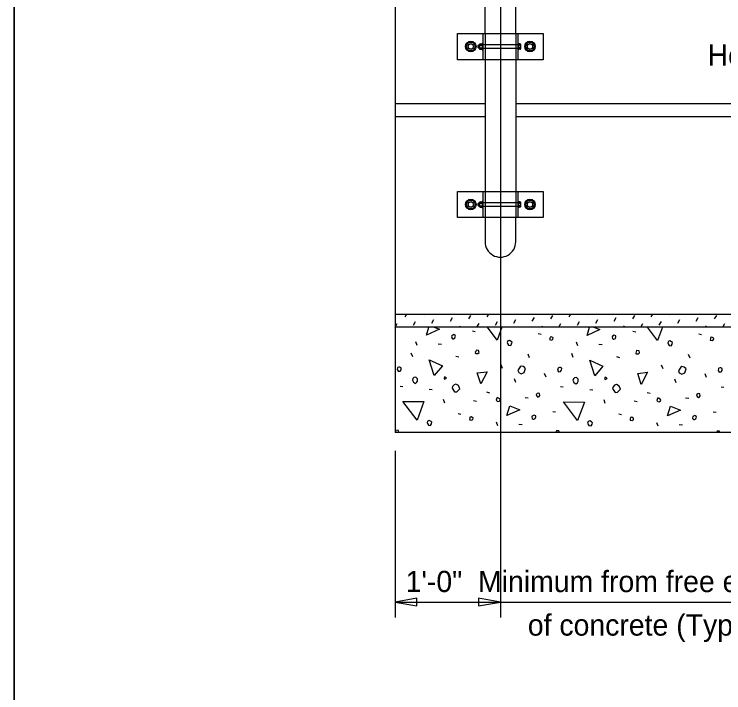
# Model space of a CAD drawing. Extents: x 0 to 41.1, y 0 to 25.9.
# Drawn here: x 0 to 6.74, y 10.63 to 17.07 of the extents above; entities that cross this region are included whole.
import ezdxf

# ---------------------------------------------------------------- set-up
doc = ezdxf.new("R2010")
doc.units = 0
for name, color, linetype in [('ActivePts-ConstElements', 7, 'Continuous'), ('CL_Major', 7, 'Continuous'), ('Dimension', 7, 'Continuous'), ('Miscellaneous', 7, 'Continuous'), ('Miscellaneous1', 7, 'Continuous'), ('SteelMisc', 7, 'Continuous'), ('SteelMisc_h', 7, 'Continuous'), ('SupstrConc', 7, 'Continuous'), ('TextStructures', 7, 'Continuous')]:
    doc.layers.add(name, color=color, linetype=linetype)

msp = doc.modelspace()

# ---------------------------------------------------------------- linework, layer by layer
at = {"layer": 'ActivePts-ConstElements'}
msp.add_lwpolyline([(0, 0), (41.0506, 0), (41.0506, 25.9461), (0, 25.9461)], close=True, dxfattribs=at)
at = {"layer": 'CL_Major'}
msp.add_line((4.615, 25.5927), (4.615, 11.342), dxfattribs=at)
at = {"layer": 'Dimension'}
for p, q in [((3.615, 12.9261), (3.615, 11.342)), ((3.6151, 11.4901), (8.3895, 11.4901))]:
    msp.add_line(p, q, dxfattribs=at)
for points in [[(3.6151, 11.4901), (3.8233, 11.4549), (3.8233, 11.5254)], [(4.6151, 11.4902), (4.4068, 11.5255), (4.4068, 11.4549)]]:
    msp.add_lwpolyline(points, close=True, dxfattribs=at)
at = {"layer": 'Miscellaneous'}
for p, q in [((4.4075, 16.7575), (4.4075, 16.7696)), ((4.4132, 16.7575), (4.4132, 16.7696)), ((4.4075, 15.2575), (4.4075, 15.2696)), ((4.4132, 15.2575), (4.4132, 15.2696)), ((3.7123, 14.1967), (3.7283, 14.2245)), ((3.8873, 14.2162), (3.8921, 14.2245)), ((4.4901, 14.1967), (4.5062, 14.2245)), ((4.6651, 14.2162), (4.6699, 14.2245)), ((5.2679, 14.1967), (5.284, 14.2245)), ((5.4429, 14.2162), (5.4477, 14.2245)), ((6.0457, 14.1967), (6.0618, 14.2245)), ((6.2207, 14.2162), (6.2255, 14.2245)), ((3.7901, 14.119), (3.8095, 14.1526)), ((3.9651, 14.1384), (3.9845, 14.172)), ((4.1401, 14.1579), (4.1595, 14.1914)), ((4.3151, 14.1773), (4.3345, 14.2109)), ((4.5679, 14.119), (4.5873, 14.1526)), ((4.7429, 14.1384), (4.7623, 14.172)), ((4.9179, 14.1579), (4.9373, 14.1914)), ((5.0929, 14.1773), (5.1123, 14.2109)), ((5.3457, 14.119), (5.3651, 14.1526)), ((5.5207, 14.1384), (5.5401, 14.172)), ((5.6957, 14.1579), (5.7152, 14.1914)), ((5.8707, 14.1773), (5.8902, 14.2109)), ((6.1235, 14.119), (6.143, 14.1526)), ((6.2985, 14.1384), (6.318, 14.172)), ((6.4735, 14.1579), (6.493, 14.1914)), ((6.6485, 14.1773), (6.668, 14.2109)), ((3.615, 14.0995), (3.6345, 14.1331)), ((4.2291, 14.0995), (4.2373, 14.1137)), ((4.3929, 14.0995), (4.4123, 14.1331)), ((5.0069, 14.0995), (5.0151, 14.1137)), ((5.1707, 14.0995), (5.1901, 14.1331)), ((5.7847, 14.0995), (5.7929, 14.1137)), ((5.9485, 14.0995), (5.9679, 14.1331)), ((6.5626, 14.0995), (6.5708, 14.1137)), ((6.7263, 14.0995), (6.7458, 14.1331)), ((4.3489, 14.0642), (4.3754, 14.0589)), ((4.9746, 14.0394), (5.0012, 14.0341)), ((5.8727, 14.0606), (5.8992, 14.0553)), ((6.4985, 14.0359), (6.525, 14.0306)), ((3.8256, 13.9263), (3.8132, 13.9599)), ((5.3494, 13.9227), (5.337, 13.9563)), ((4.0254, 13.9422), (4.0572, 13.9387)), ((5.5492, 13.9387), (5.581, 13.9351)), ((3.7832, 13.8167), (3.769, 13.852)), ((4.1933, 13.8237), (4.2216, 13.8167)), ((4.8916, 13.8078), (4.8774, 13.8432)), ((5.307, 13.8131), (5.2928, 13.8485)), ((5.7171, 13.8202), (5.7454, 13.8131)), ((6.4154, 13.8043), (6.4012, 13.8397)), ((4.6352, 13.7071), (4.6211, 13.7424)), ((6.1591, 13.7035), (6.1449, 13.7389)), ((4.7607, 13.5745), (4.7484, 13.6081)), ((5.0489, 13.6258), (5.0348, 13.6611)), ((6.5727, 13.6222), (6.5586, 13.6576)), ((3.663, 13.5409), (3.6877, 13.5374)), ((6.2846, 13.571), (6.2722, 13.6045)), ((3.9387, 13.5126), (3.9688, 13.5073)), ((4.4832, 13.4843), (4.5115, 13.4773)), ((5.1868, 13.5374), (5.2115, 13.5338)), ((5.4626, 13.5091), (5.4926, 13.5038)), ((6.007, 13.4808), (6.0353, 13.4737)), ((6.7106, 13.5338), (6.7353, 13.5303)), ((4.0872, 13.3783), (4.0749, 13.4119)), ((4.3612, 13.4048), (4.3895, 13.3977)), ((4.8491, 13.4331), (4.8792, 13.4278)), ((5.611, 13.3747), (5.5987, 13.4083)), ((6.373, 13.4295), (6.403, 13.4242)), ((5.885, 13.4013), (5.9133, 13.3942)), ((3.615, 13.2988), (3.6152, 13.2987)), ((4.2145, 13.2793), (4.241, 13.274)), ((5.1125, 13.3005), (5.1391, 13.2952)), ((5.7383, 13.2757), (5.7648, 13.2704)), ((6.6363, 13.297), (6.6629, 13.2917)), ((4.5893, 13.1626), (4.5769, 13.1962)), ((4.789, 13.1785), (4.8209, 13.175)), ((6.1131, 13.1591), (6.1007, 13.1927)), ((6.3128, 13.175), (6.3447, 13.1714))]:
    msp.add_line(p, q, dxfattribs=at)
for points in [[(3.914, 14.0253), (3.9368, 14.0995)], [(3.9869, 14.0995), (4.036, 14.0801), (3.914, 14.0253)], [(4.584, 13.9775), (4.4913, 14.0995)], [(4.6296, 14.0995), (4.584, 13.9775)], [(5.4378, 14.0217), (5.4617, 14.0995)], [(5.5018, 14.0995), (5.5598, 14.0765), (5.4378, 14.0217)], [(6.1078, 13.974), (6.0124, 14.0995)], [(6.1547, 14.0995), (6.1078, 13.974)], [(4.1615, 13.9899), (4.1685, 13.9899), (4.1827, 13.997), (4.188, 14.0129), (4.1862, 14.0217), (4.1721, 14.0288), (4.1544, 14.0182), (4.1509, 14.0076), (4.1544, 13.997), (4.1615, 13.9899)], [(5.6853, 13.9864), (5.6924, 13.9864), (5.7065, 13.9935), (5.7118, 14.0094), (5.71, 14.0182), (5.6959, 14.0253), (5.6782, 14.0147), (5.6747, 14.0041), (5.6782, 13.9935), (5.6853, 13.9864)], [(4.683, 13.9457), (4.6918, 13.9298), (4.713, 13.9263), (4.7219, 13.9422), (4.7254, 13.9563), (4.7166, 13.9652), (4.7006, 13.974), (4.6847, 13.9687), (4.6794, 13.9528), (4.683, 13.9457)], [(5.0825, 13.9811), (5.1019, 13.9758), (5.1143, 13.9846), (5.1161, 13.997), (5.1125, 14.0005), (5.0984, 14.0076), (5.086, 14.0058), (5.0843, 13.9935), (5.0825, 13.9811)], [(6.2068, 13.9422), (6.2156, 13.9263), (6.2368, 13.9227), (6.2457, 13.9387), (6.2492, 13.9528), (6.2404, 13.9616), (6.2245, 13.9705), (6.2086, 13.9652), (6.2032, 13.9493), (6.2068, 13.9422)], [(6.6063, 13.9775), (6.6257, 13.9722), (6.6381, 13.9811), (6.6399, 13.9935), (6.6363, 13.997), (6.6222, 14.0041), (6.6098, 14.0023), (6.6081, 13.9899), (6.6063, 13.9775)], [(4.3807, 13.8485), (4.4019, 13.8485), (4.4125, 13.8591), (4.4072, 13.8786), (4.3842, 13.8803), (4.3807, 13.8697), (4.3754, 13.8609), (4.3807, 13.8485), (4.3771, 13.852)], [(5.9045, 13.845), (5.9257, 13.845), (5.9363, 13.8556), (5.931, 13.875), (5.908, 13.8768), (5.9045, 13.8662), (5.8992, 13.8573), (5.9045, 13.845), (5.901, 13.8485)], [(3.9865, 13.6417), (3.9387, 13.7884), (4.0642, 13.7336), (3.9865, 13.6417)], [(5.5103, 13.6381), (5.4626, 13.7849), (5.5881, 13.7301), (5.5103, 13.6381)], [(3.6347, 13.6965), (3.6435, 13.6806), (3.663, 13.6823), (3.6718, 13.6947), (3.6736, 13.7141), (3.6612, 13.7195), (3.6524, 13.7212), (3.6418, 13.7177), (3.6382, 13.7141), (3.6347, 13.6965)], [(4.4284, 13.5604), (4.3948, 13.6647), (4.4885, 13.677), (4.4284, 13.5604)], [(4.789, 13.67), (4.812, 13.6576), (4.8421, 13.67), (4.8544, 13.7071), (4.8368, 13.7248), (4.8138, 13.7301), (4.8032, 13.723), (4.7908, 13.7035), (4.782, 13.6876), (4.789, 13.67)], [(5.1585, 13.6929), (5.1673, 13.677), (5.1868, 13.6788), (5.1956, 13.6912), (5.1974, 13.7106), (5.185, 13.7159), (5.1762, 13.7177), (5.1656, 13.7141), (5.162, 13.7106), (5.1585, 13.6929)], [(6.3128, 13.6664), (6.3358, 13.654), (6.3659, 13.6664), (6.3783, 13.7035), (6.3606, 13.7212), (6.3376, 13.7265), (6.327, 13.7195), (6.3146, 13.7), (6.3058, 13.6841), (6.3128, 13.6664)], [(6.6823, 13.6894), (6.6912, 13.6735), (6.7106, 13.6753), (6.7194, 13.6876), (6.7212, 13.7071), (6.7088, 13.7124), (6.7, 13.7141), (6.6894, 13.7106), (6.6858, 13.7071), (6.6823, 13.6894)], [(3.7796, 13.5975), (3.7902, 13.5763), (3.8079, 13.5657), (3.8221, 13.5763), (3.8291, 13.5869), (3.8291, 13.6081), (3.8132, 13.624), (3.7938, 13.6222), (3.7849, 13.6134), (3.7796, 13.5975)], [(4.0855, 13.6063), (4.1049, 13.6152), (4.0978, 13.6222), (4.0855, 13.6275), (4.0802, 13.6152), (4.0855, 13.6063)], [(5.3035, 13.5939), (5.3141, 13.5727), (5.3317, 13.5621), (5.3459, 13.5727), (5.353, 13.5833), (5.353, 13.6045), (5.337, 13.6205), (5.3176, 13.6187), (5.3088, 13.6098), (5.3035, 13.5939)], [(5.6093, 13.6028), (5.6287, 13.6116), (5.6217, 13.6187), (5.6093, 13.624), (5.604, 13.6116), (5.6093, 13.6028)], [(5.9522, 13.5568), (5.9186, 13.6611), (6.0123, 13.6735), (5.9522, 13.5568)], [(4.1562, 13.5215), (4.1792, 13.4843), (4.2021, 13.4861), (4.211, 13.4949), (4.2304, 13.5144), (4.218, 13.5444), (4.1933, 13.5586), (4.1756, 13.5515), (4.1615, 13.5374), (4.1562, 13.5215)], [(5.68, 13.5179), (5.703, 13.4808), (5.7259, 13.4826), (5.7348, 13.4914), (5.7542, 13.5109), (5.7419, 13.5409), (5.7171, 13.555), (5.6994, 13.548), (5.6853, 13.5338), (5.68, 13.5179)], [(4.9605, 13.4454), (4.9711, 13.4348), (4.9817, 13.4419), (4.9888, 13.4525), (4.9853, 13.4702), (4.9764, 13.472), (4.964, 13.4702), (4.9534, 13.4596), (4.9605, 13.4454)], [(4.5857, 13.3959), (4.5981, 13.3942), (4.6105, 13.3995), (4.614, 13.4101), (4.6087, 13.4189), (4.5981, 13.426), (4.5857, 13.4313), (4.5787, 13.4172), (4.5751, 13.4066), (4.5857, 13.3959)], [(6.1096, 13.3924), (6.1219, 13.3906), (6.1343, 13.3959), (6.1378, 13.4066), (6.1325, 13.4154), (6.1219, 13.4225), (6.1096, 13.4278), (6.1025, 13.4136), (6.0989, 13.403), (6.1096, 13.3924)], [(6.4843, 13.4419), (6.4949, 13.4313), (6.5055, 13.4384), (6.5126, 13.449), (6.5091, 13.4667), (6.5002, 13.4684), (6.4879, 13.4667), (6.4773, 13.4561), (6.4843, 13.4419)], [(3.8238, 13.2174), (3.6895, 13.3942), (3.8892, 13.3924), (3.8238, 13.2174)], [(4.6777, 13.2616), (4.7059, 13.3535), (4.7996, 13.3164), (4.6777, 13.2616)], [(5.3476, 13.2139), (5.2133, 13.3906), (5.4131, 13.3889), (5.3476, 13.2139)], [(6.2015, 13.2581), (6.2298, 13.35), (6.3235, 13.3129), (6.2015, 13.2581)], [(3.9228, 13.1856), (3.9317, 13.1697), (3.9529, 13.1661), (3.9617, 13.1821), (3.9653, 13.1962), (3.9564, 13.205), (3.9405, 13.2139), (3.9246, 13.2086), (3.9193, 13.1927), (3.9228, 13.1856)], [(4.3223, 13.2209), (4.3418, 13.2156), (4.3542, 13.2245), (4.3559, 13.2369), (4.3524, 13.2404), (4.3383, 13.2475), (4.3259, 13.2457), (4.3241, 13.2333), (4.3223, 13.2209)], [(4.9252, 13.2262), (4.9322, 13.2262), (4.9464, 13.2333), (4.9517, 13.2492), (4.9499, 13.2581), (4.9358, 13.2651), (4.9181, 13.2545), (4.9145, 13.2439), (4.9181, 13.2333), (4.9252, 13.2262)], [(5.4466, 13.1821), (5.4555, 13.1661), (5.4767, 13.1626), (5.4855, 13.1785), (5.4891, 13.1927), (5.4802, 13.2015), (5.4643, 13.2103), (5.4484, 13.205), (5.4431, 13.1891), (5.4466, 13.1821)], [(5.8462, 13.2174), (5.8656, 13.2121), (5.878, 13.2209), (5.8797, 13.2333), (5.8762, 13.2369), (5.8621, 13.2439), (5.8497, 13.2422), (5.8479, 13.2298), (5.8462, 13.2174)], [(6.449, 13.2227), (6.456, 13.2227), (6.4702, 13.2298), (6.4755, 13.2457), (6.4737, 13.2545), (6.4596, 13.2616), (6.4419, 13.251), (6.4384, 13.2404), (6.4419, 13.2298), (6.449, 13.2227)], [(3.6522, 13.0995), (3.6471, 13.1184), (3.6241, 13.1202), (3.6205, 13.1096), (3.6152, 13.1007), (3.6158, 13.0995)], [(5.1751, 13.0995), (5.1709, 13.1149), (5.1479, 13.1166), (5.1444, 13.106), (5.1404, 13.0995)], [(6.6979, 13.0995), (6.6947, 13.1113), (6.6717, 13.1131), (6.6682, 13.1025), (6.6664, 13.0995)]]:
    msp.add_lwpolyline(points, dxfattribs=at)
at = {"layer": 'Miscellaneous1'}
msp.add_lwpolyline([(0, 25.9461), (41.0506, 25.9461), (41.0506, 0), (0, 0)], close=True, dxfattribs=at)
at = {"layer": 'SteelMisc'}
for p, q in [((4.4692, 16.8894), (4.4692, 17.3653)), ((4.7609, 16.8894), (4.7609, 17.3653)), ((4.2091, 16.8894), (5.021, 16.8894)), ((4.2091, 16.6394), (4.2091, 16.8894)), ((4.4484, 16.8894), (4.4484, 16.6394)), ((4.7817, 16.8894), (4.7817, 16.6394)), ((5.021, 16.8894), (5.021, 16.6394)), ((4.4047, 16.7724), (4.4103, 16.7789)), ((4.4047, 16.7547), (4.4047, 16.7724)), ((4.4103, 16.7789), (4.4168, 16.7789)), ((4.4103, 16.749), (4.4103, 16.7789)), ((4.4168, 16.7823), (4.4168, 16.7465)), ((4.4215, 16.7774), (4.4418, 16.7774)), ((4.4217, 16.7904), (4.4418, 16.7904)), ((4.4418, 16.7947), (4.4418, 16.734)), ((4.4418, 16.7947), (4.4484, 16.7947)), ((4.4418, 16.7904), (4.4418, 16.7384)), ((4.788, 16.7947), (4.782, 16.7947)), ((4.788, 16.7947), (4.788, 16.734)), ((4.8027, 16.7903), (4.788, 16.7903)), ((4.8028, 16.7773), (4.788, 16.7773)), ((4.8078, 16.745), (4.8078, 16.7838)), ((4.4047, 16.7547), (4.4103, 16.749)), ((4.4103, 16.749), (4.4168, 16.749)), ((4.4215, 16.7514), (4.4418, 16.7514)), ((4.4218, 16.7384), (4.4418, 16.7384)), ((4.4418, 16.734), (4.4484, 16.734)), ((4.788, 16.734), (4.782, 16.734)), ((4.8028, 16.7514), (4.788, 16.7514)), ((4.8027, 16.7384), (4.788, 16.7384)), ((5.021, 16.6394), (4.2091, 16.6394)), ((4.4692, 16.6394), (4.4692, 15.3894)), ((4.7609, 16.6394), (4.7609, 15.3894)), ((4.2091, 15.3894), (5.021, 15.3894)), ((4.2091, 15.1394), (4.2091, 15.3894)), ((4.4484, 15.3894), (4.4484, 15.1394)), ((4.7817, 15.3894), (4.7817, 15.1394)), ((5.021, 15.3894), (5.021, 15.1394)), ((4.4217, 15.2904), (4.4418, 15.2904)), ((4.4418, 15.2947), (4.4418, 15.234)), ((4.4418, 15.2947), (4.4484, 15.2947)), ((4.4418, 15.2904), (4.4418, 15.2384)), ((4.788, 15.2947), (4.782, 15.2947)), ((4.788, 15.2947), (4.788, 15.234)), ((4.8027, 15.2903), (4.788, 15.2903)), ((4.4047, 15.2724), (4.4103, 15.2789)), ((4.4047, 15.2547), (4.4047, 15.2724)), ((4.4047, 15.2547), (4.4103, 15.249)), ((4.4103, 15.2789), (4.4168, 15.2789)), ((4.4103, 15.249), (4.4103, 15.2789)), ((4.4103, 15.249), (4.4168, 15.249)), ((4.4168, 15.2823), (4.4168, 15.2465)), ((4.4215, 15.2774), (4.4418, 15.2774)), ((4.4215, 15.2514), (4.4418, 15.2514)), ((4.4218, 15.2384), (4.4418, 15.2384)), ((4.4418, 15.234), (4.4484, 15.234)), ((4.788, 15.234), (4.782, 15.234)), ((4.8028, 15.2773), (4.788, 15.2773)), ((4.8028, 15.2514), (4.788, 15.2514)), ((4.8027, 15.2384), (4.788, 15.2384)), ((4.8078, 15.245), (4.8078, 15.2838)), ((5.021, 15.1394), (4.2091, 15.1394)), ((4.4691, 15.1394), (4.4691, 14.9102)), ((4.7608, 14.9102), (4.7608, 15.1394))]:
    msp.add_line(p, q, dxfattribs=at)
for points in [[(4.3124, 16.8019), (4.3557, 16.8019), (4.3774, 16.7644), (4.3557, 16.7269), (4.3124, 16.7269), (4.2907, 16.7644)], [(4.8744, 16.8019), (4.9177, 16.8019), (4.9394, 16.7644), (4.9177, 16.7269), (4.8744, 16.7269), (4.8527, 16.7644)], [(4.3124, 15.3019), (4.3557, 15.3019), (4.3774, 15.2644), (4.3557, 15.2269), (4.3124, 15.2269), (4.2907, 15.2644)], [(4.8744, 15.3019), (4.9177, 15.3019), (4.9394, 15.2644), (4.9177, 15.2269), (4.8744, 15.2269), (4.8527, 15.2644)]]:
    msp.add_lwpolyline(points, close=True, dxfattribs=at)
for centre, radius in [((4.3341, 16.7644), 0.05), ((4.3341, 16.7644), 0.025), ((4.896, 16.7644), 0.05), ((4.896, 16.7644), 0.025), ((4.3341, 15.2644), 0.05), ((4.896, 15.2644), 0.05), ((4.3341, 15.2644), 0.025), ((4.896, 15.2644), 0.025)]:
    msp.add_circle(centre, radius, dxfattribs=at)
for centre, radius, start, end in [((4.4234, 16.7838), 0.00674, 104.48908, 254.18889), ((4.4363, 16.7644), 0.0196, 138.62797, 221.37203), ((4.801, 16.7838), 0.00673, 285.7823, 75.54039), ((4.7881, 16.7644), 0.0196, 318.62797, 41.37203), ((4.4234, 16.7449), 0.00673, 105.7823, 255.54039), ((4.801, 16.7449), 0.00674, 284.48908, 74.18889), ((4.4234, 15.2838), 0.00674, 104.48908, 254.18889), ((4.801, 15.2838), 0.00673, 285.7823, 75.54039), ((4.4363, 15.2644), 0.0196, 138.62797, 221.37203), ((4.4234, 15.2449), 0.00673, 105.7823, 255.54039), ((4.801, 15.2449), 0.00674, 284.48908, 74.18889), ((4.7881, 15.2644), 0.0196, 318.62797, 41.37203)]:
    msp.add_arc(centre, radius, start, end, dxfattribs=at)
msp.add_ellipse((4.615, 14.9102), major_axis=(0, 0.1458), ratio=0.999499, start_param=1.570796, end_param=4.712389, dxfattribs=at)
at = {"layer": 'SteelMisc_h'}
for p, q in [((4.4692, 16.8894), (4.4692, 16.6394)), ((4.7609, 16.8894), (4.7609, 16.6394)), ((4.7817, 16.7789), (4.4168, 16.7789)), ((4.4168, 16.749), (4.7817, 16.749)), ((4.4692, 15.3894), (4.4692, 15.1394)), ((4.7609, 15.3894), (4.7609, 15.1394)), ((4.7817, 15.2789), (4.4168, 15.2789)), ((4.4168, 15.249), (4.7817, 15.249))]:
    msp.add_line(p, q, dxfattribs=at)
at = {"layer": 'SupstrConc'}
for p, q in [((3.615, 17.2245), (3.615, 13.0995)), ((3.615, 16.2245), (4.4692, 16.2245)), ((4.7609, 16.2245), (14.4692, 16.2245)), ((3.6151, 16.0995), (4.4692, 16.0995)), ((4.7609, 16.0995), (14.4692, 16.0995)), ((3.615, 14.2245), (16.002, 14.2245)), ((16.002, 14.0995), (3.615, 14.0995)), ((16.002, 13.0995), (3.615, 13.0995))]:
    msp.add_line(p, q, dxfattribs=at)

# ---------------------------------------------------------------- texts
at = {"layer": 'TextStructures'}
for s, p in [('Hog Rings @ 2\'-0" Centers', (6.5816, 16.5823)), ('1\'-0"  Minimum from free end ', (3.7161, 11.5845)), ('of concrete (Typ.)', (4.8754, 11.171))]:
    msp.add_text(s, height=0.2016, dxfattribs=at).set_placement(p)

doc.saveas('drawing.dxf')
